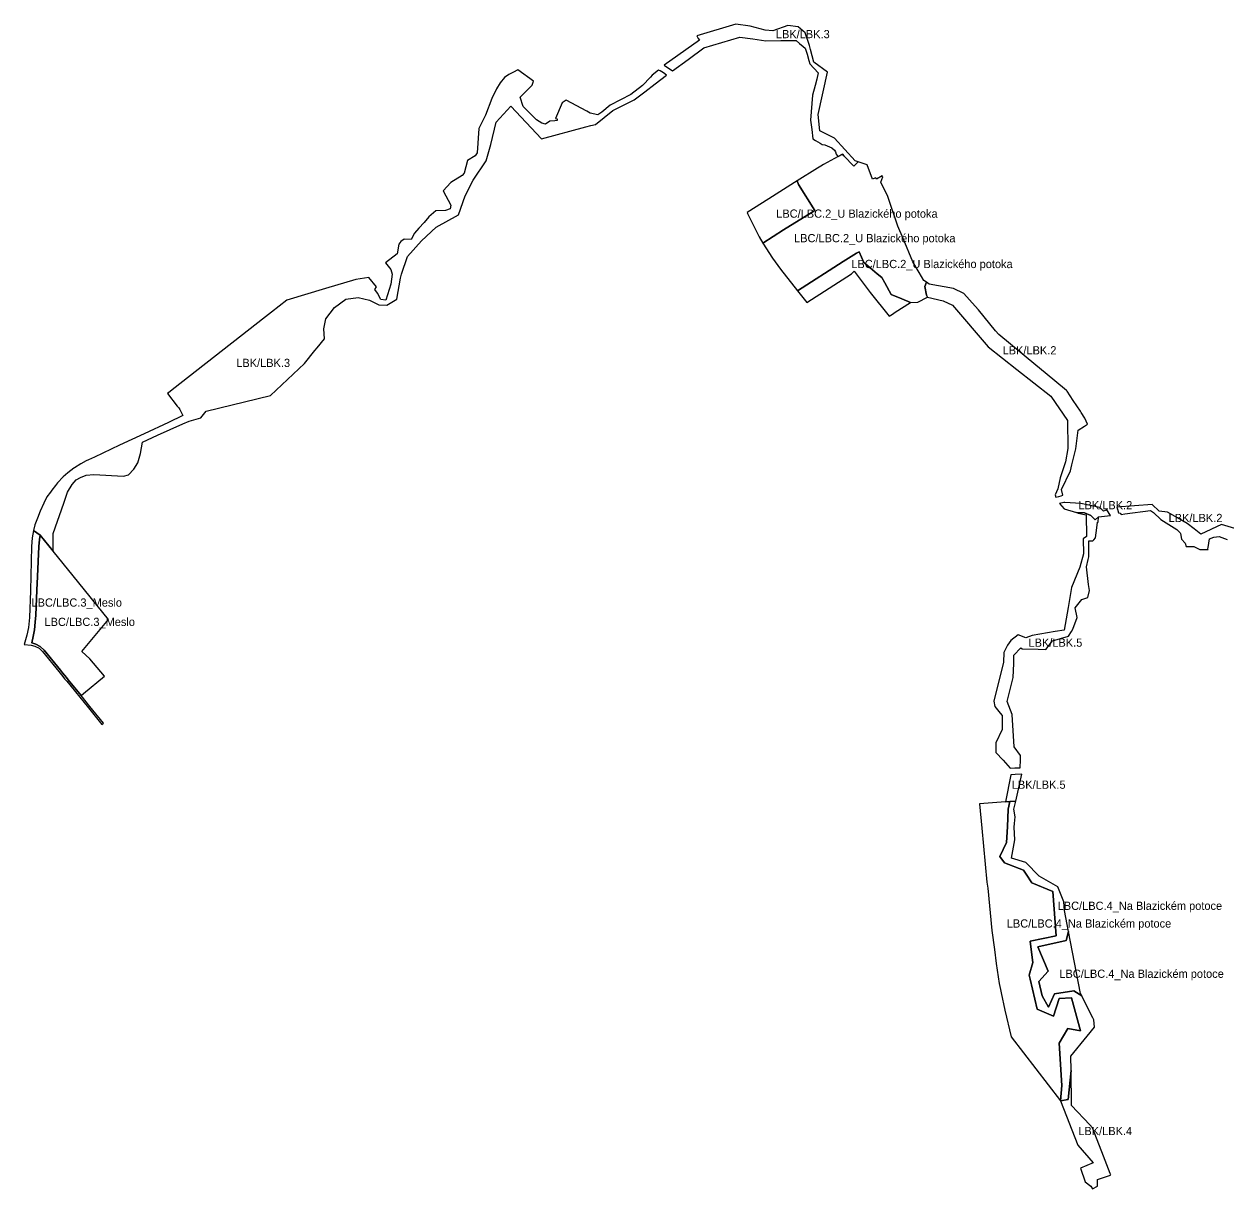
# Model space of a CAD drawing. Extents: x -521980 to -518833, y -1141793 to -1140093.
# Drawn here: x -521980 to -520226, y -1141793 to -1140093 of the extents above; entities that cross this region are included whole.
import ezdxf

# ---------------------------------------------------------------- set-up
doc = ezdxf.new("R2010")
doc.units = 0
for name, color, linetype in [('91270013', 7, 'Continuous'), ('91270023', 7, 'Continuous'), ('91280013', 7, 'Continuous')]:
    doc.layers.add(name, color=color, linetype=linetype)

msp = doc.modelspace()

# ---------------------------------------------------------------- linework, layer by layer
at = {"layer": '91270013'}
for points in [[(-520902.19, -1140412.67), (-520887.82, -1140434.78), (-520876.46, -1140450.75), (-520851.49, -1140482.48), (-520784.75, -1140439.67), (-520781.06, -1140437.3), (-520765.49, -1140427.57), (-520761.78, -1140425.25), (-520754.76, -1140441.12), (-520752.54, -1140443.09), (-520735.34, -1140457.3), (-520728.4, -1140462.65), (-520724, -1140470.78), (-520714.97, -1140487.48), (-520699.14, -1140493.81), (-520686.89, -1140499.45), (-520675.92, -1140498.77), (-520661.91, -1140491.42), (-520663.43, -1140488.4), (-520666, -1140475.86), (-520663.2, -1140469.86), (-520666.98, -1140467.24), (-520673.87, -1140455.8), (-520683.48, -1140439.85), (-520697.54, -1140405.82), (-520704.93, -1140387.92), (-520719.64, -1140344.89), (-520729.96, -1140323.84), (-520727.12, -1140316.09), (-520728.21, -1140314.51), (-520736.37, -1140319.22), (-520737.2, -1140317.47), (-520738.8, -1140318.04), (-520742.16, -1140319.24), (-520750.13, -1140298.42), (-520763.01, -1140294.16), (-520769.34, -1140300.61), (-520783.73, -1140285.25), (-520785.74, -1140282.9), (-520792.29, -1140286.44), (-520813.67, -1140297.99), (-520817.67, -1140300.36), (-520822.46, -1140303.46), (-520852.13, -1140321.93), (-520849.95, -1140326.96), (-520826.19, -1140365.01), (-520830.07, -1140367.42), (-520872.15, -1140393.54), (-520902.19, -1140412.67)], [(-521966.23, -1140832.06), (-521968.4, -1140842.82), (-521969.35, -1140855.23), (-521970.78, -1140919.37), (-521970.73, -1140920.13), (-521972.01, -1140959.19), (-521973.56, -1140973.69), (-521975.77, -1140984.83), (-521980.02, -1140998.54), (-521969.71, -1140999.55), (-521964.16, -1141000.63), (-521958.05, -1141003.66), (-521952.92, -1141008.37), (-521929.14, -1141037.67), (-521925.3, -1141042.86), (-521920.31, -1141048.71), (-521917.71, -1141051.91), (-521886.17, -1141090.77), (-521866.46, -1141115.05), (-521865.29, -1141114.1), (-521864.13, -1141113.16), (-521883.81, -1141088.91), (-521896.82, -1141072.9), (-521915.45, -1141049.99), (-521918.24, -1141046.46), (-521923.77, -1141039.61), (-521925.13, -1141037.95), (-521927.04, -1141035.61), (-521950.59, -1141006.47), (-521956.25, -1141001.25), (-521962.85, -1140997.93), (-521968.74, -1140996.16), (-521966.75, -1140986.81), (-521964.79, -1140976.78), (-521963.61, -1140965.78), (-521962.64, -1140955.52), (-521961.27, -1140919.13), (-521960.41, -1140899.15), (-521958.48, -1140855.25), (-521957.55, -1140845.37), (-521956.51, -1140838.94), (-521966.23, -1140832.06)], [(-520436.83, -1141511), (-520448.25, -1141503.52), (-520476.51, -1141508.33), (-520485.33, -1141527.78), (-520494.54, -1141511.04), (-520499.43, -1141490.33), (-520485.81, -1141474.99), (-520501.13, -1141439.65), (-520459.35, -1141430.33), (-520456.11, -1141417.28), (-520462.06, -1141386.7), (-520463.1, -1141373.93), (-520471.76, -1141351.9), (-520499.06, -1141336.21), (-520518.61, -1141316.36), (-520539.2, -1141310.09), (-520534.35, -1141283.17), (-520535.3, -1141264.93), (-520534.84, -1141259.42), (-520534.05, -1141249.88), (-520535.7, -1141238.47), (-520533.07, -1141226.75), (-520541.94, -1141227.47), (-520544.19, -1141238.83), (-520545.37, -1141264.63), (-520546.39, -1141287.04), (-520556.25, -1141307.68), (-520549.32, -1141316.76), (-520521.95, -1141327.46), (-520517.94, -1141333.55), (-520509.58, -1141346.13), (-520479.06, -1141358.55), (-520474.23, -1141423.42), (-520512.06, -1141431.3), (-520509.69, -1141451.35), (-520508.38, -1141462.38), (-520513.39, -1141481.08), (-520512.09, -1141486.67), (-520501.99, -1141530.25), (-520478.09, -1141540.57), (-520469.99, -1141514.94), (-520451.9, -1141513.8), (-520438.57, -1141562.32), (-520457.06, -1141558.71), (-520469.63, -1141579.9), (-520465.85, -1141641.84), (-520467.83, -1141664.2), (-520456.84, -1141662.39), (-520452.43, -1141620.06), (-520452.66, -1141599.19), (-520428.95, -1141569.87), (-520418.4, -1141556.83), (-520419, -1141546.21), (-520420.69, -1141542.88), (-520435.68, -1141513.27), (-520436.83, -1141511)]]:
    msp.add_lwpolyline(points, dxfattribs=at)
at = {"layer": '91270023'}
for points in [[(-520902.19, -1140412.67), (-520872.15, -1140393.54), (-520830.07, -1140367.42), (-520826.19, -1140365.01), (-520849.95, -1140326.96), (-520852.13, -1140321.93), (-520855.89, -1140324.19), (-520893.13, -1140348.26), (-520925.04, -1140368.05), (-520924.44, -1140369.44), (-520915.77, -1140387.04), (-520907.24, -1140403.74), (-520902.19, -1140412.67)], [(-520686.89, -1140499.45), (-520699.14, -1140493.81), (-520714.97, -1140487.48), (-520724, -1140470.78), (-520728.4, -1140462.65), (-520735.34, -1140457.3), (-520752.54, -1140443.09), (-520754.76, -1140441.12), (-520761.78, -1140425.25), (-520765.49, -1140427.57), (-520781.06, -1140437.3), (-520784.75, -1140439.67), (-520851.49, -1140482.48), (-520837.71, -1140499.35), (-520772.84, -1140457.31), (-520769.04, -1140453.82), (-520745.68, -1140484.57), (-520717.71, -1140519.42), (-520712.75, -1140516.21), (-520708.82, -1140513.67), (-520686.89, -1140499.45)], [(-521937.7, -1140862.04), (-521956.51, -1140838.94), (-521957.55, -1140845.37), (-521958.48, -1140855.25), (-521960.41, -1140899.15), (-521961.27, -1140919.13), (-521962.64, -1140955.52), (-521963.61, -1140965.78), (-521964.79, -1140976.78), (-521966.75, -1140986.81), (-521968.74, -1140996.16), (-521962.85, -1140997.93), (-521956.25, -1141001.25), (-521950.59, -1141006.47), (-521927.04, -1141035.61), (-521925.13, -1141037.95), (-521923.77, -1141039.61), (-521918.24, -1141046.46), (-521915.45, -1141049.99), (-521896.82, -1141072.9), (-521893.06, -1141069.8), (-521862.5, -1141044.56), (-521884.07, -1141019.15), (-521895.5, -1141008.4), (-521856.78, -1140962.03), (-521908.14, -1140898.33), (-521937.7, -1140862.04)], [(-520467.83, -1141664.2), (-520465.85, -1141641.84), (-520469.63, -1141579.9), (-520457.06, -1141558.71), (-520438.57, -1141562.32), (-520451.9, -1141513.8), (-520469.99, -1141514.94), (-520478.09, -1141540.57), (-520501.99, -1141530.25), (-520512.09, -1141486.67), (-520513.39, -1141481.08), (-520508.38, -1141462.38), (-520509.69, -1141451.35), (-520512.06, -1141431.3), (-520474.23, -1141423.42), (-520479.06, -1141358.55), (-520509.58, -1141346.13), (-520517.94, -1141333.55), (-520521.95, -1141327.46), (-520549.32, -1141316.76), (-520556.25, -1141307.68), (-520546.39, -1141287.04), (-520545.37, -1141264.63), (-520544.19, -1141238.83), (-520541.94, -1141227.47), (-520548.16, -1141227.97), (-520585.84, -1141231.02), (-520582.4, -1141266.58), (-520575.29, -1141345.21), (-520573.91, -1141353.97), (-520567.96, -1141415.92), (-520564.35, -1141443.41), (-520561.66, -1141463.92), (-520557.24, -1141493.24), (-520555.49, -1141501.75), (-520554.45, -1141506.79), (-520549.23, -1141532.17), (-520539.75, -1141570.9), (-520467.83, -1141664.2)], [(-520436.83, -1141511), (-520438.53, -1141507.64), (-520456.11, -1141417.28), (-520459.35, -1141430.33), (-520501.13, -1141439.65), (-520485.81, -1141474.99), (-520499.43, -1141490.33), (-520494.54, -1141511.04), (-520485.33, -1141527.78), (-520476.51, -1141508.33), (-520448.25, -1141503.52), (-520436.83, -1141511)]]:
    msp.add_lwpolyline(points, dxfattribs=at)
at = {"layer": '91280013'}
for points in [[(-520763.01, -1140294.16), (-520767.33, -1140292.73), (-520797.63, -1140259.52), (-520818.83, -1140248.97), (-520821.47, -1140225.09), (-520807.65, -1140163.22), (-520827.76, -1140148.83), (-520832.38, -1140130.38), (-520833.95, -1140124.09), (-520840.13, -1140106.03), (-520850.56, -1140096.88), (-520865.88, -1140095.27), (-520887.39, -1140102.82), (-520898.59, -1140102.13), (-520920.41, -1140096.1), (-520941.45, -1140093.01), (-520998.41, -1140110.24), (-520996.26, -1140113.95), (-520994.7, -1140116.62), (-521045.99, -1140153.16), (-521034.09, -1140161.31), (-521011.08, -1140144.62), (-520988.07, -1140127.93), (-520961.82, -1140119.95), (-520935.57, -1140111.96), (-520916.78, -1140114.77), (-520897.98, -1140117.57), (-520875.72, -1140117.25), (-520853.46, -1140116.93), (-520848.47, -1140121.24), (-520843.47, -1140125.55), (-520840.13, -1140128.04), (-520837.6, -1140136.97), (-520834.99, -1140146), (-520833.53, -1140151.04), (-520821.16, -1140164.16), (-520823.57, -1140173.47), (-520825.99, -1140182.77), (-520829.57, -1140196.57), (-520832.49, -1140233.14), (-520830.83, -1140246.91), (-520829.16, -1140260.67), (-520825.47, -1140262.86), (-520821.79, -1140265.06), (-520818.64, -1140266.93), (-520815.5, -1140268.8), (-520811.67, -1140269.37), (-520801.58, -1140273.72), (-520797.56, -1140277.1), (-520796.05, -1140279.66), (-520795.15, -1140282.87), (-520793.72, -1140284.66), (-520792.29, -1140286.44), (-520785.74, -1140282.9), (-520783.73, -1140285.25), (-520769.34, -1140300.61), (-520763.01, -1140294.16)], [(-521937.7, -1140862.04), (-521937.7, -1140842.11), (-521937.7, -1140836.22), (-521922.02, -1140791.92), (-521916.45, -1140776.17), (-521909.81, -1140765.14), (-521903.79, -1140757.88), (-521897.69, -1140754.5), (-521889.21, -1140751.5), (-521878.09, -1140750.44), (-521834.89, -1140752.79), (-521827.42, -1140750.62), (-521819.79, -1140742.52), (-521813.81, -1140733.11), (-521809.93, -1140719.56), (-521807.36, -1140702.96), (-521785.36, -1140693.05), (-521748.53, -1140676.5), (-521739.27, -1140672.34), (-521722.24, -1140667.6), (-521714.47, -1140657.84), (-521620.49, -1140635.2), (-521571.05, -1140588.16), (-521555.68, -1140569.39), (-521552.45, -1140565.44), (-521541.63, -1140552.23), (-521542.41, -1140537.54), (-521539.58, -1140523.18), (-521527.29, -1140506.41), (-521510.34, -1140494.68), (-521492.65, -1140492.08), (-521476.06, -1140495.98), (-521462.16, -1140502.96), (-521450.52, -1140503.04), (-521436.3, -1140494.58), (-521430.55, -1140463.89), (-521429.44, -1140457.98), (-521420.52, -1140431.99), (-521399.96, -1140409.23), (-521378.73, -1140389.63), (-521346.04, -1140371.4), (-521336.24, -1140343.91), (-521324.74, -1140320.75), (-521305.66, -1140292.85), (-521298.91, -1140268.76), (-521291.01, -1140236.12), (-521269.84, -1140212.73), (-521224.97, -1140260.52), (-521160.59, -1140243.23), (-521153.02, -1140241.2), (-521146.28, -1140239.39), (-521133.54, -1140229.36), (-521120.8, -1140219.34), (-521105.37, -1140211.55), (-521089.93, -1140203.76), (-521074.47, -1140191.91), (-521059.01, -1140180.06), (-521042.52, -1140167.42), (-521047.19, -1140164.44), (-521051.86, -1140161.45), (-521054.36, -1140160.13), (-521063.7, -1140167.77), (-521066.01, -1140170.35), (-521077.51, -1140182.69), (-521094.81, -1140196.05), (-521124.89, -1140211.23), (-521136.78, -1140221.72), (-521142.98, -1140225.64), (-521153.92, -1140223.1), (-521159.02, -1140220.32), (-521188.9, -1140204.31), (-521194.92, -1140208.09), (-521204.62, -1140230.71), (-521202.15, -1140231.14), (-521202.32, -1140233.95), (-521205.52, -1140234.19), (-521212.75, -1140234.73), (-521219.26, -1140238.96), (-521224.62, -1140237.78), (-521232.49, -1140232.94), (-521251.89, -1140213.49), (-521256.3, -1140199.5), (-521238.42, -1140182.36), (-521236.81, -1140176.19), (-521259.67, -1140159.99), (-521265.75, -1140163.05), (-521272.67, -1140166.78), (-521278.81, -1140171.17), (-521285.21, -1140178.6), (-521290.54, -1140187.61), (-521297.37, -1140201.85), (-521306.79, -1140226.13), (-521316.46, -1140245.31), (-521319.14, -1140281.01), (-521321.89, -1140285.5), (-521333.16, -1140292.26), (-521337.76, -1140310.68), (-521340.77, -1140314.23), (-521357.43, -1140324.38), (-521368.43, -1140336.25), (-521357.5, -1140357.21), (-521358.18, -1140362.8), (-521365.2, -1140365.12), (-521379.07, -1140365.7), (-521389.35, -1140374.32), (-521396.32, -1140382.62), (-521403.86, -1140390.75), (-521410.38, -1140398.05), (-521415.37, -1140407.41), (-521425.52, -1140407.15), (-521430.32, -1140410.33), (-521433.21, -1140414.4), (-521435.44, -1140428.3), (-521452.48, -1140441.66), (-521444.82, -1140451.17), (-521442.88, -1140458.09), (-521445.06, -1140472.47), (-521451.98, -1140495.75), (-521459.62, -1140494.93), (-521464.21, -1140485.93), (-521468.11, -1140480.32), (-521465.61, -1140476.61), (-521476.87, -1140463.06), (-521496.06, -1140465.78), (-521540.23, -1140479.04), (-521596.59, -1140495.96), (-521619, -1140513.52), (-521623.29, -1140516.88), (-521627.73, -1140520.35), (-521763.73, -1140626.86), (-521766.84, -1140629.25), (-521770.53, -1140631.96), (-521756.45, -1140650.36), (-521754.23, -1140653.26), (-521752.49, -1140655.36), (-521748.38, -1140664.24), (-521769.34, -1140674.65), (-521804.78, -1140690.88), (-521822.52, -1140699.01), (-521840.82, -1140707.39), (-521877.29, -1140724.81), (-521885.86, -1140728.85), (-521889.34, -1140730.49), (-521897.11, -1140734.61), (-521906.16, -1140740.38), (-521907.36, -1140741.3), (-521915.99, -1140747.92), (-521922.69, -1140753.87), (-521930.99, -1140762.54), (-521933.99, -1140766.2), (-521939.58, -1140773.02), (-521941.53, -1140776.07), (-521946.81, -1140782.96), (-521951.34, -1140792.2), (-521956.64, -1140803.89), (-521960.5, -1140813.97), (-521964.35, -1140823.92), (-521966.23, -1140832.06), (-521956.51, -1140838.94), (-521937.7, -1140862.04)], [(-520661.91, -1140491.42), (-520639.11, -1140496.92), (-520625.42, -1140503.23), (-520573.29, -1140563.98), (-520531.68, -1140596.93), (-520481.74, -1140636.06), (-520457.81, -1140671.57), (-520457.2, -1140712.56), (-520460.77, -1140732), (-520466.36, -1140749.44), (-520468.2, -1140755.18), (-520471.47, -1140771.35), (-520475.64, -1140780.08), (-520474.64, -1140783.36), (-520470.41, -1140782.37), (-520466.78, -1140781.53), (-520464.48, -1140780.47), (-520466.39, -1140772.32), (-520453.26, -1140745.12), (-520451.15, -1140736.24), (-520445.6, -1140712.87), (-520442.27, -1140685.74), (-520432.59, -1140679.54), (-520428.23, -1140676.75), (-520432.32, -1140668.06), (-520437.69, -1140659.73), (-520438.76, -1140658.07), (-520449.35, -1140642.33), (-520458.26, -1140628.64), (-520459.31, -1140627.54), (-520490.09, -1140602.11), (-520503.8, -1140590.78), (-520557.7, -1140546.26), (-520562.49, -1140540.48), (-520587.65, -1140510.13), (-520592.52, -1140504.62), (-520608.7, -1140486.32), (-520623.97, -1140478.75), (-520659.41, -1140472.47), (-520663.2, -1140469.86), (-520666, -1140475.86), (-520663.43, -1140488.4), (-520661.91, -1140491.42)], [(-520444.45, -1140805.57), (-520432.63, -1140806.38), (-520423.57, -1140810.07), (-520417.22, -1140816.48), (-520412.34, -1140812.28), (-520394.93, -1140810.08), (-520400.31, -1140802.09), (-520404.93, -1140803.86), (-520410.6, -1140798.4), (-520438.34, -1140792.64), (-520461.64, -1140791.05), (-520463.08, -1140791.37), (-520469.2, -1140792.72), (-520462.48, -1140800.42), (-520444.45, -1140805.57)], [(-520444.45, -1140805.57), (-520442.16, -1140806.74), (-520430.39, -1140809.03), (-520430.02, -1140840.87), (-520434.81, -1140844.08), (-520434.39, -1140866.1), (-520439.44, -1140885.49), (-520451.95, -1140915.2), (-520454.37, -1140929.78), (-520456.82, -1140944.51), (-520462.25, -1140977.23), (-520475.75, -1140979.18), (-520509.19, -1140985.26), (-520518.62, -1140988.49), (-520529.52, -1140984.06), (-520540.36, -1140992.71), (-520545.15, -1140999.12), (-520550.66, -1141010.15), (-520551.07, -1141024.16), (-520556.5, -1141046.1), (-520561.24, -1141065.24), (-520565.18, -1141081.15), (-520563.4, -1141088.78), (-520555.74, -1141098.46), (-520552.84, -1141102.13), (-520552.98, -1141119.42), (-520553, -1141122.43), (-520562.26, -1141141.67), (-520562.26, -1141155.75), (-520551.66, -1141167.29), (-520541.06, -1141178.84), (-520534.49, -1141178.34), (-520530.26, -1141178.39), (-520526.48, -1141178.44), (-520526.38, -1141166.45), (-520526.34, -1141160.53), (-520535.5, -1141147.72), (-520538.13, -1141100.63), (-520545.68, -1141081.75), (-520537, -1141046.7), (-520536.12, -1141026.2), (-520535.76, -1141013.89), (-520525.61, -1141003.28), (-520523.55, -1141004.78), (-520500.6, -1141005.26), (-520489.07, -1141005.5), (-520479.55, -1140993.19), (-520456.05, -1140986), (-520451.99, -1140979.48), (-520449.86, -1140976.07), (-520443.57, -1140958.81), (-520446.27, -1140944.76), (-520436.62, -1140932.6), (-520427.82, -1140929.68), (-520425.67, -1140919.72), (-520426.8, -1140910.65), (-520429.99, -1140884.98), (-520427.4, -1140874.32), (-520426.37, -1140870.34), (-520426.43, -1140847.27), (-520420.69, -1140847.27), (-520419.27, -1140845.56), (-520416.81, -1140842.62), (-520414.81, -1140828.01), (-520413.68, -1140819.71), (-520412.85, -1140819.83), (-520412.34, -1140812.28), (-520417.22, -1140816.48), (-520423.57, -1140810.07), (-520432.63, -1140806.38), (-520444.45, -1140805.57)], [(-520213.5, -1140828.96), (-520232.81, -1140823.41), (-520263.21, -1140837.13), (-520273.01, -1140829.49), (-520282.82, -1140821.86), (-520297.29, -1140813.47), (-520311.77, -1140805.08), (-520323.97, -1140803.87), (-520333.88, -1140793.93), (-520385.85, -1140798.14), (-520384.61, -1140800.83), (-520383.09, -1140806.25), (-520380.85, -1140806.63), (-520379.43, -1140808.81), (-520373.88, -1140807.82), (-520336.41, -1140802.99), (-520331.98, -1140805.6), (-520332, -1140805.6), (-520321.54, -1140816.1), (-520302.1, -1140827.97), (-520298.02, -1140830.46), (-520293.05, -1140835.38), (-520292.87, -1140836.23), (-520291.11, -1140844.75), (-520286.12, -1140850.49), (-520284.67, -1140855.24), (-520273.49, -1140855.19), (-520264.75, -1140859.75), (-520252.57, -1140859.91), (-520253.04, -1140858.58), (-520252.48, -1140856.73), (-520250.57, -1140844.07), (-520243.98, -1140841.86), (-520236.26, -1140840.92), (-520224.47, -1140845.06)], [(-520541.94, -1141227.47), (-520533.07, -1141226.75), (-520524.27, -1141187.6), (-520534.17, -1141188.18), (-520540.34, -1141188.43), (-520548.16, -1141227.97), (-520541.94, -1141227.47)], [(-520467.83, -1141664.2), (-520442.29, -1141729.04), (-520420.15, -1141754.6), (-520438.59, -1141762.62), (-520431.99, -1141782.5), (-520423.68, -1141788.92), (-520421.03, -1141792.82), (-520413.91, -1141788.74), (-520413.8, -1141779.11), (-520396.49, -1141772.96), (-520394.48, -1141772.19), (-520395.26, -1141770.17), (-520405.02, -1141744.98), (-520421.11, -1141703.69), (-520425.12, -1141699.44), (-520451.86, -1141671.07), (-520452.43, -1141620.06), (-520456.84, -1141662.39), (-520467.83, -1141664.2)]]:
    msp.add_lwpolyline(points, dxfattribs=at)

# ---------------------------------------------------------------- texts
at = {"layer": '91270013'}
for s, rotation, p in [('LBC/LBC.2_U Blazického potoka', 0, (-520856.53, -1140411.44)), ('LBC/LBC.3_Meslo', 360, (-521969.1, -1140943.15)), ('LBC/LBC.4_Na Blazickém potoce', 0, (-520471.93, -1141385.61))]:
    msp.add_text(s, height=12, rotation=rotation, dxfattribs=at).set_placement(p)
at = {"layer": '91270023'}
for s, rotation, p in [('LBC/LBC.2_U Blazického potoka', 0, (-520882.56, -1140375.64)), ('LBC/LBC.2_U Blazického potoka', 360, (-520773.06, -1140449.14)), ('LBC/LBC.3_Meslo', 0, (-521950.19, -1140971.33)), ('LBC/LBC.4_Na Blazickém potoce', 0, (-520546.19, -1141411.44)), ('LBC/LBC.4_Na Blazickém potoce', 0, (-520469.49, -1141484.75))]:
    msp.add_text(s, height=12, rotation=rotation, dxfattribs=at).set_placement(p)
at = {"layer": '91280013'}
for s, rotation, p in [('LBK/LBK.3', 0, (-520883.06, -1140113.69)), ('LBK/LBK.2', 360, (-520552.26, -1140575.07)), ('LBK/LBK.3', 0, (-521670.38, -1140593.44)), ('LBK/LBK.2', 0, (-520441.63, -1140801.07)), ('LBK/LBK.2', 0, (-520310.11, -1140819.71)), ('LBK/LBK.5', 360, (-520514.49, -1141001.64)), ('LBK/LBK.5', 360, (-520538.89, -1141208.89)), ('LBK/LBK.4', 360, (-520441.85, -1141714.2))]:
    msp.add_text(s, height=12, rotation=rotation, dxfattribs=at).set_placement(p)

doc.saveas('drawing.dxf')
